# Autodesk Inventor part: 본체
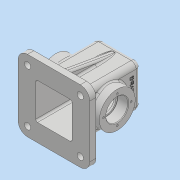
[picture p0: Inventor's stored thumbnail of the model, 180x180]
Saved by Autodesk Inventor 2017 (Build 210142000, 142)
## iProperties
Part Number: 본체
Material: 일반
Document SubType Name: Modeling
Designer: MRC
Density: 1 g/cm^3
Appearance: 기본값
Author: MRC
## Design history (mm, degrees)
sketch "스케치1"
  geometry: L1 (34, 34)-(-34, 34); L2 (-34, 34)-(-34, -34); L3 (-34, -34)-(34, -34); L4 (34, -34)-(34, 34); L5 (34, 34)-(-34, -34); L6 (-34, 34)-(34, -34); 1 further point
  constraints: 12 end point, 2 midpoint, 2 parallel, 1 horizontal, 1 perpendicular
  dimensions: "d0" = 68 distance of L3.end L2.end; "d1" = 68 distance of L2.end L1.end
extrude "돌출1" new body sketch "스케치1" stored distance "d2" = 105; taper "d3" = 0 deg
sketch "스케치2"
  geometry: L1 (34, 34)-(-34, 34) reference; L2 (-34, 34)-(-34, -34) reference; L3 (-34, -34)-(34, -34) reference; L4 (34, -34)-(34, 34) reference; L5 (57, 57)-(-57, 57); L6 (-57, 57)-(-57, -57); L7 (-57, -57)-(57, -57); L8 (57, -57)-(57, 57); L9 (57, 57)-(-57, -57); L10 (-57, 57)-(57, -57); 1 further point
  constraints: 12 end point, 2 midpoint, 2 parallel, 1 horizontal, 1 perpendicular
  dimensions: "d4" = 114 distance of L7.end L6.end; "d5" = 114 distance of L6.end L5.end
extrude "돌출2" join sketch "스케치2" distance "d6" = 10; taper "d7" = 0 deg
sketch "스케치3"
  geometry: L1 (91, -105)-(-23, -105) reference; C1 r 28.5 at (34, -53); 1 further point
  constraints: 1 centre point, 1 vertical alignment
  dimensions: "d8" = 57 diameter of C1; "d9" = 52 distance from line of L1 C1.centre
extrude "돌출3" join sketch "스케치3" distance "d10" = 15; taper "d11" = 0 deg
sketch "스케치4"
  geometry: C1 r 28.5 at (0, 0) reference; C2 r 17.5 at (0, 0); 1 further point
  constraints: 1 centre point, 1 concentric
  dimensions: "d12" = 35 diameter of C2
extrude "돌출4" cut sketch "스케치4" distance "d13" = 17; taper "d14" = 0 deg
sketch "스케치5"
  geometry: L1 (29, 29)-(-29, 29); L2 (-29, 29)-(-29, -29); L3 (-29, -29)-(29, -29); L4 (29, -29)-(29, 29); L5 (29, 29)-(-29, -29); L6 (-29, 29)-(29, -29); 1 further point
  constraints: 12 end point, 2 midpoint, 2 parallel, 1 horizontal, 1 perpendicular
  dimensions: "d15" = 58 distance of L3.end L2.end; "d16" = 58 distance of L2.end L1.end
extrude "돌출5" cut sketch "스케치5" distance "d17" = 100; taper "d18" = 0 deg
sketch "스케치6"
  geometry: C1 r 17.5 at (0, 0) reference; C2 r 15 at (0, 0); 1 further point
  constraints: 1 centre point, 1 concentric
  dimensions: "d19" = 30 diameter of C2
extrude "돌출6" cut sketch "스케치6" stored distance "d20" = 100; taper "d21" = 0 deg
sketch "스케치7"
  geometry: C1 r 20 at (0, 0); 1 further point
  constraints: 1 centre point, 1 coincident
  dimensions: "d22" = 40 diameter of C1
extrude "돌출7" join sketch "스케치7" distance "d23" = 10; taper "d24" = -8 deg
sketch "스케치8"
  geometry: C1 r 18.595 at (0, 0) reference; 1 further point
  constraints: 1 coincident
hole "구멍1" sketch "스케치8" at (0, 0) diameter "d25" = 22.835; stored, may be unused: countersink angle "d29" = 90 deg, drill point angle "d31" = 118 deg; dims "d26" = 15, "d27" = 4, "d28" = 2, "d30" = 15
sketch "스케치9"
  geometry: L1 (-42.5, -57)-(-42.5, 57) reference; L2 (-42.5, 49)-(42.569, 34); L3 (-52.5, 57)-(-42.5, 57) reference; L4 (52.5, 34)-(-42.5, 34) reference; 1 further point
  constraints: 2 end point, 2 point on line
  dimensions: "d32" = 8 distance from line of L3 L2.start; "d33" = 10 deg angle of L3 L2
feature "리브1" sketch "스케치9" dims "d34" = 1, "d35" = 10, "d36" = 0, "d37" = 0, "d38" = 1, "d39" = 1
fillet "모깎기1" dims "d53" = 8
fillet "모깎기2" dims "d54" = 8
fillet "모깎기3" dims "d55" = 3
fillet "모깎기4" dims "d56" = 3
fillet "모깎기5" dims "d57" = 3
fillet "모깎기6" dims "d58" = 3
fillet "모깎기7" dims "d59" = 15
sketch "스케치12"
  geometry: A1 r 15 centre (-42, 42) between (-42, 57) and (-57, 42) reference; A2 r 15 centre (-42, -42) between (-57, -42) and (-42, -57) reference; A3 r 15 centre (42, -42) between (42, -57) and (57, -42) reference; A4 r 15 centre (42, 42) between (57, 42) and (42, 57) reference; 5 further points
  constraints: 4 coincident
hole "구멍2" sketch "스케치12" at (42, -42), (-42, -42), (-42, 42), (42, 42) diameter "d60" = 10; stored, may be unused: countersink angle "d64" = 90 deg, drill point angle "d66" = 118 deg; dims "d61" = 15, "d62" = 18, "d63" = 2, "d65" = 15
fillet "모깎기8" dims "d67" = 0.3
fillet "모깎기9" dims "d68" = 3
chamfer "모따기1" distance "d69" = 1; stored, may be unused: second distance "d70" = 2, angle "d71" = 45 deg
sketch "스케치13"
  geometry: L1 (-8, 0)-(-8, -84) reference; L2 (7.405, 18)-(44.595, 18) reference; 2 further points
  constraints: 1 other
  dimensions: "d72" = 34 distance from line of point (26, -7) L1; "d73" = 25 distance from line of point (26, -7) L2
feature "엠보싱1" sketch "스케치13" dims "d0" = 68, "d1" = 68, "d74" = 0.5, "d75" = 0
fillet "모깎기10" dims "d76" = 3
fillet "모깎기11" dims "d77" = 3
sketch "스케치14"
  geometry: C1 r 28.5 at (0, 0) reference; 5 further points
  constraints: 2 horizontal alignment, 2 vertical alignment
  dimensions: "d78" = 44 distance of point (0, -22) point (0, 22); "d79" = 44 distance of point (-22, 0) point (22, 0); "d80" = 22 distance of C1.centre point (22, 0) (= 0.5 x d79); "d81" = 22 distance of C1.centre point (0, 22) (= 0.5 x d78)
hole "구멍3" sketch "스케치14" at (0, 22), (22, 0), (0, -22), (-22, 0) diameter "d82" = 3.242; stored, may be unused: countersink angle "d86" = 90 deg, drill point angle "d88" = 118 deg; dims "d83" = 8, "d84" = 18, "d85" = 2, "d87" = 10
node "솔리드1"
mirror "미러1"
mirror "미러2"
mirror "미러3"
